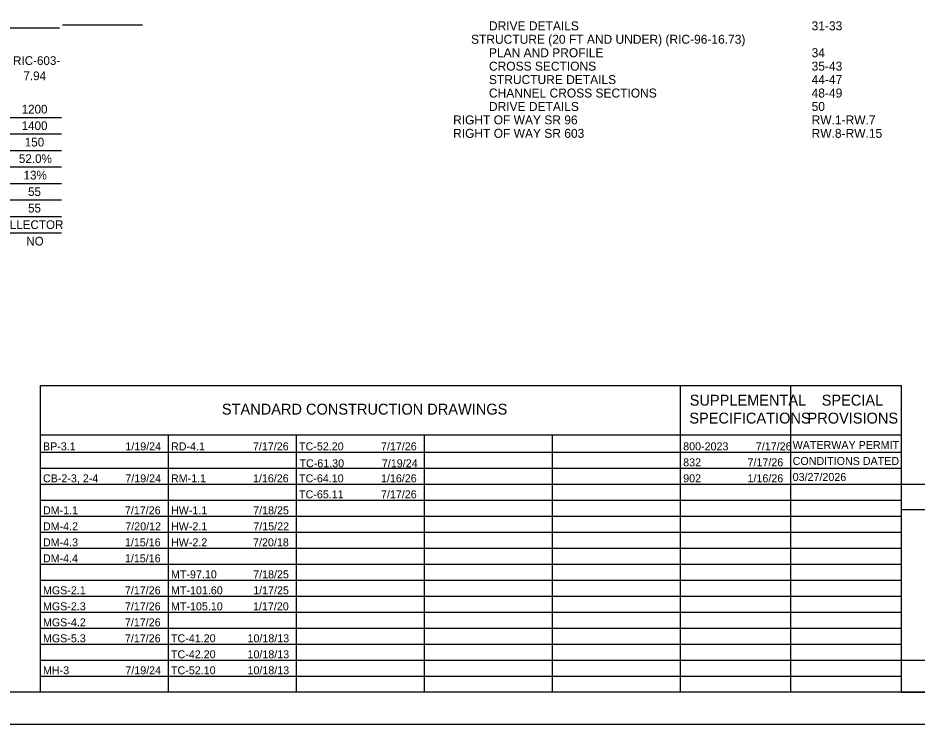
# Model space of a CAD drawing. Extents: x 0 to 70.2, y 0 to 31.4.
# Drawn here: x 7.05 to 21.1, y 0 to 11.03 of the extents above; entities that cross this region are included whole.
import ezdxf

# ---------------------------------------------------------------- set-up
doc = ezdxf.new("R2010")
doc.units = 0
for name, color, linetype in [('Default', 7, 'Continuous'), ('SH_Border', 7, 'Continuous'), ('SH_Cut_Line', 7, 'Continuous'), ('SH_Data', 7, 'Continuous'), ('SH_Text', 7, 'Continuous')]:
    doc.layers.add(name, color=color, linetype=linetype)

msp = doc.modelspace()

# ---------------------------------------------------------------- linework, layer by layer
at = {"layer": 'Default'}
for p, q in [((6.876, 9.48), (7.736, 9.48)), ((6.876, 9.222), (7.736, 9.222)), ((6.876, 8.965), (7.736, 8.965)), ((6.876, 8.707), (7.736, 8.707)), ((6.876, 8.449), (7.736, 8.449)), ((6.876, 8.191), (7.736, 8.191)), ((6.876, 7.933), (7.736, 7.933)), ((6.876, 7.675), (7.736, 7.675))]:
    msp.add_line(p, q, dxfattribs=at)
at = {"layer": 'SH_Border'}
msp.add_lwpolyline([(1.5, 21.5), (33.5, 21.5), (33.5, 0.5), (1.5, 0.5)], close=True, dxfattribs=at)
at = {"layer": 'SH_Cut_Line'}
msp.add_lwpolyline([(0, 0), (34, 0), (34, 22), (0, 22)], close=True, dxfattribs=at)
at = {"layer": 'SH_Data'}
for p, q in [((7.7, 10.877), (3.347, 10.877)), ((9, 10.922), (7.75, 10.922)), ((7.403, 5.292), (20.853, 5.292)), ((7.403, 0.5), (7.403, 5.292)), ((17.403, 0.5), (17.403, 5.292)), ((19.128, 0.5), (19.128, 5.292)), ((20.853, 0.5), (20.853, 5.292)), ((20.853, 0.5), (20.853, 5.292)), ((7.403, 4.521), (20.853, 4.521)), ((9.403, 0.5), (9.403, 4.521)), ((11.403, 0.5), (11.403, 4.521)), ((13.403, 0.5), (13.403, 4.521)), ((15.403, 0.5), (15.403, 4.521)), ((7.403, 4.25), (20.853, 4.25)), ((7.403, 4), (20.853, 4)), ((7.403, 3.75), (20.853, 3.75)), ((20.853, 0.5), (20.853, 3.75)), ((20.853, 3.75), (23.653, 3.75)), ((7.403, 3.5), (20.853, 3.5)), ((7.403, 3.25), (20.853, 3.25)), ((20.853, 3.35), (23.653, 3.35)), ((7.403, 3), (20.853, 3)), ((7.403, 2.75), (20.853, 2.75)), ((7.403, 2.5), (20.853, 2.5)), ((7.403, 2.25), (20.853, 2.25)), ((7.403, 2), (20.853, 2)), ((7.403, 1.75), (20.853, 1.75)), ((7.403, 1.5), (20.853, 1.5)), ((7.403, 1.25), (20.853, 1.25)), ((7.403, 1), (20.853, 1)), ((7.403, 0.75), (20.853, 0.75)), ((20.853, 0.5), (23.653, 0.5))]:
    msp.add_line(p, q, dxfattribs=at)
msp.add_lwpolyline([(20.853, 0.5), (20.853, 1), (23.653, 1), (23.653, 0.5)], close=True, dxfattribs=at)

# ---------------------------------------------------------------- texts
at = {"layer": 'Default'}
for s, height, p in [('RIC-603-', 0.1359, (6.977, 10.3)), ('7.94', 0.1359, (7.139, 10.062)), ('1200', 0.1359, (7.111, 9.541)), ('1400', 0.1359, (7.111, 9.283)), ('150', 0.1359, (7.16, 9.026)), ('52.0%', 0.1359, (7.068, 8.768)), ('13%', 0.1359, (7.141, 8.51)), ('55', 0.1359, (7.211, 8.252)), ('55', 0.1359, (7.211, 7.994)), ('MAJOR COLLECTOR', 0.13594, (5.966, 7.736)), ('NO', 0.1359, (7.183, 7.478)), ('BP-3.1', 0.125, (7.444, 4.277)), ('1/19/24', 0.125, (8.731, 4.277)), ('RD-4.1', 0.125, (9.444, 4.277)), ('7/17/26', 0.125, (10.724, 4.277)), ('TC-52.20', 0.125, (11.444, 4.277)), ('7/17/26', 0.125, (12.724, 4.277)), ('800-2023', 0.125, (17.444, 4.277)), ('7/17/26', 0.125, (18.579, 4.277)), ('WATERWAY PERMIT', 0.125, (19.154, 4.298)), ('TC-61.30', 0.125, (11.451, 4.012)), ('7/19/24', 0.125, (12.738, 4.012)), ('832', 0.125, (17.444, 4.027)), ('7/17/26', 0.125, (18.449, 4.027)), ('CONDITIONS DATED', 0.125, (19.154, 4.048)), ('CB-2-3, 2-4', 0.125, (7.444, 3.777)), ('7/19/24', 0.125, (8.731, 3.777)), ('RM-1.1', 0.125, (9.444, 3.777)), ('1/16/26', 0.125, (10.724, 3.777)), ('TC-64.10', 0.125, (11.444, 3.777)), ('1/16/26', 0.125, (12.724, 3.777)), ('902', 0.125, (17.444, 3.777)), ('1/16/26', 0.125, (18.449, 3.777)), ('03/27/2026', 0.125, (19.154, 3.798)), ('TC-65.11', 0.125, (11.444, 3.527)), ('7/17/26', 0.125, (12.724, 3.527)), ('DM-1.1', 0.125, (7.444, 3.277)), ('7/17/26', 0.125, (8.724, 3.277)), ('HW-1.1', 0.125, (9.444, 3.277)), ('7/18/25', 0.125, (10.728, 3.277)), ('DM-4.2', 0.125, (7.444, 3.027)), ('7/20/12', 0.125, (8.73, 3.027)), ('HW-2.1', 0.125, (9.444, 3.027)), ('7/15/22', 0.125, (10.73, 3.027)), ('DM-4.3', 0.125, (7.444, 2.777)), ('1/15/16', 0.125, (8.724, 2.777)), ('HW-2.2', 0.125, (9.444, 2.777)), ('7/20/18', 0.125, (10.726, 2.777)), ('DM-4.4', 0.125, (7.444, 2.527)), ('1/15/16', 0.125, (8.724, 2.527)), ('MT-97.10', 0.125, (9.444, 2.277)), ('7/18/25', 0.125, (10.728, 2.277)), ('MGS-2.1', 0.125, (7.444, 2.027)), ('7/17/26', 0.125, (8.724, 2.027)), ('MT-101.60', 0.125, (9.444, 2.027)), ('1/17/25', 0.125, (10.728, 2.027)), ('MGS-2.3', 0.125, (7.444, 1.777)), ('7/17/26', 0.125, (8.724, 1.777)), ('MT-105.10', 0.125, (9.444, 1.777)), ('1/17/20', 0.125, (10.725, 1.777)), ('MGS-4.2', 0.125, (7.444, 1.527)), ('7/17/26', 0.125, (8.724, 1.527)), ('7/17/26', 0.125, (8.724, 1.277)), ('10/18/13', 0.125, (10.639, 1.277)), ('MGS-5.3', 0.125, (7.444, 1.277)), ('TC-41.20', 0.125, (9.444, 1.277)), ('TC-42.20', 0.125, (9.444, 1.027)), ('10/18/13', 0.125, (10.639, 1.027)), ('MH-3', 0.125, (7.444, 0.777)), ('7/19/24', 0.125, (8.731, 0.777)), ('TC-52.10', 0.125, (9.444, 0.777)), ('10/18/13', 0.125, (10.639, 0.777))]:
    msp.add_text(s, height=height, dxfattribs=at).set_placement(p)
at = {"layer": 'SH_Text'}
for s, height, p in [('DRIVE DETAILS', 0.14, (14.41, 10.841)), ('31-33', 0.14, (19.45, 10.841)), ('STRUCTURE (20 FT AND UNDER) (RIC-96-16.73)', 0.14, (14.13, 10.631)), ('PLAN AND PROFILE', 0.14, (14.41, 10.421)), ('34', 0.14, (19.45, 10.421)), ('CROSS SECTIONS', 0.14, (14.41, 10.211)), ('35-43', 0.14, (19.45, 10.211)), ('STRUCTURE DETAILS', 0.14, (14.41, 10.001)), ('44-47', 0.14, (19.45, 10.001)), ('CHANNEL CROSS SECTIONS', 0.14, (14.41, 9.791)), ('48-49', 0.14, (19.45, 9.791)), ('DRIVE DETAILS', 0.14, (14.41, 9.581)), ('50', 0.14, (19.45, 9.581)), ('RIGHT OF WAY SR 96', 0.14, (13.85, 9.371)), ('RW.1-RW.7', 0.14, (19.45, 9.371)), ('RIGHT OF WAY SR 603', 0.14, (13.85, 9.161)), ('RW.8-RW.15', 0.14, (19.45, 9.161)), ('SUPPLEMENTAL', 0.17, (17.546, 4.976)), ('SPECIAL', 0.17, (19.607, 4.976)), ('STANDARD CONSTRUCTION DRAWINGS', 0.17, (10.239, 4.836)), ('SPECIFICATIONS', 0.17, (17.54, 4.696)), ('PROVISIONS', 0.17, (19.386, 4.696))]:
    msp.add_text(s, height=height, dxfattribs=at).set_placement(p)

doc.saveas('drawing.dxf')
